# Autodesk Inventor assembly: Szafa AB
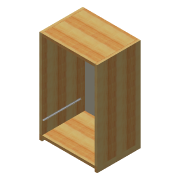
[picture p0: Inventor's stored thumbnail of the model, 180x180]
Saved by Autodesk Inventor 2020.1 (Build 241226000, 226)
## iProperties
Created: 2005-10
Part Number: Szafa AB
Document SubType Name: Assembly
Designer: F.Stasiak
Manager: www.cadconsulting.pl
Company: Fabian Stasiak CAD Consulting
Author: F.Stasiak
Subject: Zbiór ćwiczeń. Autodesk Inventor 2020. Kurs podstawowy
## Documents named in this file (3)
- C:\2020_Kurs_podstawowy\R6 Zespoły\Szyki\Szafa AB.iam
- C:\2020_Kurs_podstawowy\R6 Zespoły\Szyki\Skrzynia szafki AB.iam
- C:\2020_Kurs_podstawowy\R6 Zespoły\Szyki\Szuflada AB.iam
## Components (2 placed, 2 different names)
1. Skrzynia szafki AB:1 [sub-assembly] — Zestawiający:1, Zestawiający:2, Zestawiający:3
2. Szuflada AB:1 [sub-assembly] — Zestawiający:1, Zestawiający:2, Zestawiający:3
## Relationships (3: Mate 3)
- Zestawiający:1 [Mate]: Skrzynia szafki AB:1 ↔ Szuflada AB:1
- Zestawiający:2 [Mate]: Skrzynia szafki AB:1 ↔ Szuflada AB:1
- Zestawiający:3 [Mate]: Skrzynia szafki AB:1 ↔ Szuflada AB:1
